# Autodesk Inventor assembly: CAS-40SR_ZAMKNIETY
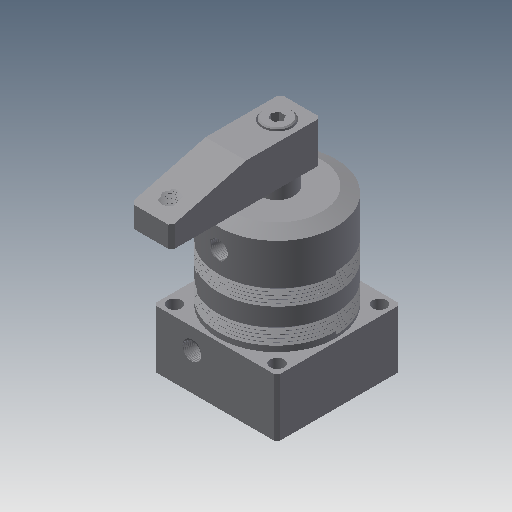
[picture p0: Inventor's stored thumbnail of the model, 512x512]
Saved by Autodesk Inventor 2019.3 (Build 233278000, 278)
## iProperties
Created: 2009-09
Part Number: CAS-40SR_ZAMKNIETY
Material: Ogólny
Document SubType Name: Assembly
Designer: CADENGINEERING4
Sending System: PRO/ENGINEER BY PARAMETRIC TECHNOLOGY CORPORATION, 2007170
Preprocessor: PRO/ENGINEER BY PARAMETRIC TECHNOLOGY CORPORATION, 2007170
Title: CAS-40S_ASM
Author: Administrator
Revision Number: 2LAST_VERSION
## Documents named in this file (7)
- D:\Vault_2016\Projekty\STRONA\Pneumatic\Line ; Pipe connecct - type\cas-40s_asm\CAS-40SR_ZAMKNIETY.iam
- D:\Vault_2016\Projekty\STRONA\Pneumatic\Line ; Pipe connecct - type\cas-40s_asm\CAS-40BT.ipt
- D:\Vault_2016\Projekty\STRONA\Pneumatic\Line ; Pipe connecct - type\cas-40s_asm\CAS-40HSG.ipt
- D:\Vault_2016\Projekty\STRONA\Pneumatic\Line ; Pipe connecct - type\cas-40s_asm\CAS-40HG.ipt
- D:\Vault_2016\Projekty\STRONA\Pneumatic\Line ; Pipe connecct - type\cas-40s_asm\M4.ipt
- D:\Vault_2016\Projekty\STRONA\Pneumatic\Line ; Pipe connecct - type\cas-40s_asm\CAS-32SYB.ipt
- D:\Vault_2016\Projekty\STRONA\Pneumatic\Line ; Pipe connecct - type\cas-40s_asm\M8LC.ipt
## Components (9 placed, 9 different names)
1. CAS-40BT_0 — Zestawiające:5, Kątowe:1, Równoległe:1
2. CAS-40HSG_1 — Zestawiające:1, Zestawiające:2, Zestawiające:4, Zestawiające:5
3. CAS-40HG_2
4. M4_3
5. M4_4
6. M4_5
7. M4_6
8. CAS-32SYB_7 — Zestawiające:1, Zestawiające:3, Zestawiające:4, Kątowe:1, Równoległe:1
9. M8LC_8 — Zestawiające:2, Zestawiające:3
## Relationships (7: Mate 5, Angle 1, Flush 1)
- Zestawiające:1 [Mate]: CAS-40HSG_1 ↔ CAS-32SYB_7
- Zestawiające:2 [Mate]: CAS-40HSG_1 ↔ M8LC_8
- Zestawiające:3 [Mate]: CAS-32SYB_7 ↔ M8LC_8
- Zestawiające:4 [Mate]: CAS-40HSG_1 ↔ CAS-32SYB_7
- Zestawiające:5 [Mate]: CAS-40BT_0 ↔ CAS-40HSG_1
- Kątowe:1 [Angle]: CAS-40BT_0 ↔ CAS-32SYB_7
- Równoległe:1 [Flush]: CAS-40BT_0 ↔ CAS-32SYB_7
